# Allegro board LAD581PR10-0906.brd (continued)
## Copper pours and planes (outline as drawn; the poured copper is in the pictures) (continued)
PWR_VGA_CORE_LGATE1 on IN1 (solid shape): 238.9,60.54 237.95,59.59 237.31,59.59 237.12,59.78 237.12,60.22 238.14,61.24 238.9,61.24
PWR_VGA_CORE_LGATE1 on IN1 (solid shape): 250.52,62.06 251.41,62.06 251.73,61.75 251.73,61.37 251.6,61.24 249.25,61.24 249,61.49 249,61.68 249.7,62.38 250.2,62.38
PWR_VGA_CORE_LGATE2 on TOP (solid shape): 251.73,62.7 252.68,62.7 252.73,62.65 252.73,62.49 252.68,62.44 250.65,62.44 250.52,62.57 250.52,62.83 250.65,62.95 251.47,62.95
PWR_VGA_CORE_LGATE2 on TOP (solid shape): 240.58,68.02 240.58,67.44 240.81,67.21 240.81,66.51 240.68,66.38 239.66,66.38 239.35,66.7 239.35,67.94 239.56,68.16 240.44,68.16
PWR_VGA_CORE_LGATE2 on IN1 (solid shape): 240.87,67.14 240.87,64.86 240.7,64.7 239.76,64.7 239.65,64.81 239.65,66.11 239.66,66.13 239.66,67.02 239.85,67.21 240.81,67.21
PWR_VGA_CORE_LGATE2 on IN1 (solid shape): 251.86,63.46 251.86,62.64 251.6,62.38 250.71,62.38 250.46,62.64 249.82,62.64 249.51,62.95 249.51,63.4 249.82,63.71 251.6,63.71
PWR_VGA_CORE_PHASE1 on TOP (solid shape): 252.73,61.42 252.73,61.29 251.4,59.96 249.49,59.96 249.39,60.06 249.39,60.7 249.48,60.79 250.97,60.79 251.66,61.49 252.66,61.49
PWR_VGA_CORE_PHASE1 on TOP (solid shape): 241.38,64.48 241.38,60.56 242.58,59.35 242.58,57.09 242.3,56.8 237.2,56.8 236.95,57.06 236.95,59.05 237.18,59.29 238.15,59.29 238.51,59.65 238.51,64.54 238.63,64.67 241.19,64.67
PWR_VGA_CORE_PHASE1 on BOTTOM (solid shape): 242.58,63.24 242.58,58.06 242.39,57.87 238.64,57.87 238.46,58.06 238.46,63.16 238.83,63.53 242.3,63.53
PWR_VGA_CORE_PHASE1 on IN1 (solid shape): 242.52,60.22 242.52,59.21 242.39,59.08 241.63,59.08 241.5,59.21 241.5,60.16 241.7,60.35 242.39,60.35
PWR_VGA_CORE_PHASE1 on IN1 (solid shape): 251.92,60.67 251.92,60.48 251.16,59.71 249.76,59.71 249.44,60.03 249.44,60.79 249.63,60.98 251.6,60.98
PWR_VGA_CORE_PHASE2 on TOP (solid shape): 251.92,64.22 251.92,63.84 252.73,63.04 252.73,62.93 252.66,62.87 251.75,62.87 250.9,63.71 249.7,63.71 249.63,63.78 249.63,64.41 249.7,64.48 251.66,64.48
PWR_VGA_CORE_PHASE2 on TOP (solid shape): 244.49,73.87 244.49,72.29 244.04,71.84 243.73,71.84 243.6,71.72 243.6,67.65 243.73,67.52 244.04,67.52 244.17,67.4 244.17,65.68 243.92,65.43 241.19,65.43 241.06,65.56 241.06,67.3 240.73,67.63 240.73,71.92 242.08,73.27 242.08,74.32 242.14,74.38 243.98,74.38
PWR_VGA_CORE_PHASE2 on BOTTOM (solid shape): 244.87,72.8 244.87,66.11 244.51,65.75 244.49,65.75 244.17,65.43 241.19,65.43 240.93,65.68 240.93,67.02 240.81,67.14 239.34,67.14 239.31,67.12 238.6,67.12 238.55,67.16 238.55,70.71 238.59,70.74 239.13,70.74 241.31,72.92 241.63,72.92 242.08,73.37 244.3,73.37
PWR_VGA_CORE_PHASE2 on IN1 (solid shape): 251.92,65.18 251.92,63.97 251.86,63.91 250.78,63.91 250.52,64.16 250.52,65.24 250.71,65.43 251.66,65.43
PWR_VGA_CORE_PHASE2 on IN1 (solid shape): 245.49,66.42 245.49,65.69 245.14,65.35 241.33,65.35 241.06,65.62 241.06,66.76 241.19,66.89 241.2,66.88 241.58,66.88 241.59,66.89 245.02,66.89
PWR_VGA_CORE_UGATE1 on TOP (solid shape): 244.3,60.73 244.3,59.84 244.17,59.71 243.35,59.71 243.16,59.9 243.16,60.98 243.22,61.05 243.98,61.05
PWR_VGA_CORE_UGATE1 on TOP (solid shape): 253.55,61.02 253.55,59.9 253.51,59.86 253.51,58.95 253.44,58.89 253.11,58.89 253.04,58.97 253.04,59.89 253.32,60.17 253.32,61.02 253.38,61.08 253.49,61.08
PWR_VGA_CORE_UGATE1 on IN1 (solid shape): 245.25,60.41 245.25,60.03 244.93,59.71 243.35,59.71 243.09,59.97 243.09,60.54 243.28,60.73 244.93,60.73
PWR_VGA_CORE_UGATE1 on IN1 (solid shape): 253.76,59.9 253.76,59.02 253.38,58.63 252.11,58.63 251.86,58.89 251.86,59.84 252.11,60.1 253.57,60.1
PWR_VGA_CORE_UGATE2 on TOP (solid shape): 247.66,68.54 247.66,67.84 247.16,67.33 245.51,67.33 245.38,67.46 245.38,68.1 245.51,68.22 246.65,68.22 247.16,68.73 247.47,68.73
PWR_VGA_CORE_UGATE2 on TOP (solid shape): 253.62,65.44 253.62,65.28 253.63,65.28 253.63,64.54 253.54,64.44 253.54,63.33 253.48,63.27 253.38,63.27 253.32,63.33 253.32,64.35 253.13,64.54 253.13,65.43 253.25,65.56 253.51,65.56
PWR_VGA_CORE_UGATE2 on IN1 (solid shape): 253.82,65.68 253.82,64.48 253.63,64.29 252.81,64.29 252.17,64.92 252.17,66.19 252.49,66.51 253,66.51
PWR_VGA_CORE_UGATE2 on IN1 (solid shape): 248.93,68.6 248.93,67.97 248.74,67.78 246.84,67.78 246.65,67.97 246.65,68.6 246.87,68.83 248.71,68.83
RING2 on BOTTOM (solid shape): 18.43,17.49 18.43,16.41 18.35,16.33 16.68,16.33 16.65,16.36 16.65,17.59 16.88,17.82 18.09,17.82
RING2 on BOTTOM (solid shape): 21.92,38.52 23.44,38.52 23.51,38.46 23.51,38.33 23.44,38.27 21.98,38.27 21.86,38.14 20.97,38.14 20.84,38.27 20.84,38.52 20.97,38.65 21.79,38.65
RING2 on IN5 (solid shape): 21.98,38.46 21.98,38.21 20.9,37.13 19.89,37.13 19.89,37.51 21.03,38.65 21.79,38.65
RING2 on IN5 (solid shape): 18.05,18.78 18.05,17.38 17.92,17.25 17.09,17.25 16.9,17.44 16.9,18.43 17.38,18.9 17.92,18.9
RING2_R on BOTTOM (solid shape): 16.99,19.32 16.99,18.24 16.49,17.73 16.49,15.86 16.94,15.41 16.96,15.39 16.96,14.91 16.97,14.91 16.97,13.96 16.82,13.81 16.22,13.81 16.08,13.96 16.08,14.38 16.1,14.4 16.1,15.09 15.79,15.39 15.79,16.44 15.61,16.62 15.01,16.62 14.91,16.72 14.91,17.31 15.34,17.74 15.34,18.21 15.33,18.22 15.33,18.54 15.89,19.1 15.89,19.37 16.04,19.52 16.79,19.52
RING2_R on IN3 (solid shape): 16.94,19.38 16.94,18.6 16.65,18.31 16.19,18.31 15.9,18.6 15.9,19.37 16.05,19.52 16.8,19.52
RING2_R on IN5 (solid shape): 16.94,19.39 16.94,18.87 16.47,18.4 16.04,18.4 15.86,18.58 15.86,19.4 16,19.54 16.79,19.54
RJ45_CT on BOTTOM (solid shape): 225.87,158.96 225.87,156.35 225.68,156.16 224.6,156.16 224.35,156.42 224.35,158.07 222.75,159.66 210.81,159.66 210.77,159.7 210.77,160.36 211.15,160.74 224.09,160.74
RT8812_PVCC on TOP (solid shape): 249.44,64.16 249.44,63.78 250.14,63.08 250.33,63.08 250.39,63.02 250.39,62.51 250.59,62.32 252.68,62.32 252.73,62.27 252.73,62.11 252.68,62.06 249.76,62.06 249.51,62.32 249.51,62.83 249.12,63.21 248.62,63.21 248.43,63.4 248.43,64.16 248.49,64.22 249.38,64.22
SLEEVE on BOTTOM (solid shape): 18.49,22.06 18.49,21.11 18.23,20.85 16.84,20.85 16.65,21.04 16.65,22.18 16.71,22.24 18.31,22.24
SLEEVE on BOTTOM (solid shape): 22.17,38.91 23.44,38.91 23.51,38.84 23.51,38.72 23.44,38.65 21.98,38.65 21.86,38.78 20.78,38.78 20.31,38.31 19.51,38.31 19.38,38.44 19.38,38.78 19.7,39.1 21.98,39.1
SLEEVE on IN5 (solid shape): 17.79,21.82 17.79,20.94 17.67,20.81 16.84,20.81 16.65,21 16.65,21.57 16.14,22.08 16.14,22.71 16.33,22.9 16.71,22.9
SLEEVE on IN5 (solid shape): 20.51,38.64 20.51,38.45 19.19,37.13 18.74,37.13 18.49,37.38 18.49,37.76 19,38.27 19,38.33 19.49,38.82 20.33,38.82
SLEEVE_R on BOTTOM (solid shape): 16.47,23.12 16.47,20.87 16.89,20.45 16.89,20.03 16.6,19.73 16.02,19.73 15.71,19.43 15.71,19.2 15.57,19.06 14.84,19.06 14.64,19.25 14.64,19.58 15.36,20.29 15.36,20.98 14.98,21.36 14.98,21.91 15.01,21.93 15.57,21.93 15.76,22.12 15.76,23.11 15.87,23.22 16.38,23.22
SLEEVE_R on IN1 (solid shape): 15.71,19.39 15.71,18.74 15.34,18.38 15.03,18.38 14.66,18.74 14.66,19.39 14.8,19.53 15.57,19.53
SLEEVE_R on IN4 (solid shape): 15.72,19.38 15.72,18.25 15.52,18.05 15.43,18.05 14.66,18.82 14.66,19.39 14.81,19.54 15.56,19.54
SNB_VCCIO on BOTTOM (solid shape): 94.99,99.37 94.99,98.3 94.63,97.94 94.63,97.07 94.56,97.01 94.06,97.01 93.11,97.96 93.11,99.27 93.26,99.43 94.94,99.43
SPK_L+_CONN on TOP (solid shape): 39.36,11.36 39.36,10.7 39.3,10.64 38.97,10.64 38.71,10.38 38.07,10.38 37.93,10.24 36.5,10.24 36.4,10.34 36.4,11.14 36.97,11.7 39.02,11.7
SPK_L+_CONN on TOP (solid shape): 29.96,13.75 29.96,13.06 30.22,12.81 31,12.81 31.25,12.55 31.25,11.85 31.19,11.79 28.65,11.79 28.4,12.05 28.4,12.61 28.45,12.66 29.24,12.66 29.36,12.79 29.36,13.74 29.41,13.79 29.92,13.79
SPK_L+_CONN on TOP (solid shape): 22.6,28.15 22.6,27.94 22.45,27.79 22.43,27.77 22.08,27.77 22.05,27.74 22.04,27.74 22.03,27.74 22.01,27.74 22.01,27.72 21.86,27.57 21.86,27.13 21.81,27.08 21.28,27.08 21.24,27.12 21.24,27.61 21.33,27.71 21.34,27.71 21.41,27.77 21.47,27.84 21.48,27.85 21.53,27.9 21.53,27.94 21.56,27.97 21.56,28.15 21.67,28.26 22.5,28.26
SPK_L+_CONN on BOTTOM (solid shape): 40.23,13.07 40.23,10.78 39.9,10.45 38.49,10.45 38.34,10.59 38.34,10.82 38.57,11.04 38.71,11.04 39.34,11.67 39.34,13.05 39.52,13.23 40.08,13.23
SPK_L+_CONN on IN2 (solid shape): 22.62,28.24 22.62,26.47 22.37,26.22 21.54,27.05 21.54,28.17 21.67,28.3 22.55,28.3
SPK_L+_CONN on IN2 (solid shape): 28.7,13.01 30,13.01 30.21,12.81 30.21,12.11 30.08,11.98 28.33,11.98 28.02,12.3 28.02,12.43 28.37,12.78 28.37,13.06 28.43,13.12 28.59,13.12
SPK_L-_CONN on TOP (solid shape): 33.6,14.2 33.6,13.7 34.62,12.68 34.62,12.55 34.11,12.05 33.73,12.05 32.52,13.25 32.52,14.27 32.59,14.33 33.48,14.33
SPK_L-_CONN on TOP (solid shape): 38.35,9.22 40.72,9.22 40.72,8.17 36.28,8.17 35.93,8.52 35.93,9.35 36.12,9.54 38.03,9.54
SPK_L-_CONN on TOP (solid shape): 24.38,28.12 24.38,27.81 24.44,27.75 24.44,27.08 24.41,27.05 23.86,27.05 23.75,27.16 23.75,27.65 23.62,27.78 23.46,27.78 23.34,27.89 23.34,28.14 23.46,28.26 24.24,28.26
SPK_L-_CONN on BOTTOM (solid shape): 33.98,15.73 33.98,13.32 33.86,13.19 32.71,13.19 32.59,13.32 32.59,15.86 32.65,15.92 33.79,15.92
SPK_L-_CONN on BOTTOM (solid shape): 41.52,13.02 41.52,9.35 40.63,8.46 36.04,8.46 35.95,8.55 35.95,9.39 36.12,9.57 40.1,9.57 40.5,9.97 40.5,13 40.74,13.23 41.31,13.23
SPK_L-_CONN on IN2 (solid shape): 33.37,15.2 33.37,13.25 33.31,13.19 32.59,13.19 32.46,13.32 32.46,14.71 32.08,15.09 32.08,15.16 32.59,15.66 32.91,15.66
SPK_L-_CONN on IN2 (solid shape): 24.43,28.14 24.43,27.67 24.73,27.37 24.73,26.5 24.46,26.24 23.84,26.24 23.71,26.36 23.71,27.16 23.35,27.52 23.35,28.2 23.41,28.26 24.3,28.26
SPK_L-_CONN on IN2 (solid shape): 25.1,24.79 25.1,23.63 25.07,23.62 24.87,23.29 25.07,22.97 25.1,22.96 25.1,22.25 25.07,22.24 24.87,21.91 25.07,21.59 25.1,21.58 25.1,20.87 25.07,20.85 24.87,20.53 25.07,20.21 25.1,20.2 25.1,19.49 25.07,19.47 24.9,19.01 25.36,18.83 25.39,18.84 25.6,18.63 25.73,18.63 25.8,18.57 25.8,17.87 25.54,17.61 25.1,17.61 24.08,18.63 24.08,18.89 24.2,19.15 24.08,19.42 24.08,20.27 24.2,20.53 24.08,20.8 24.08,21.65 24.2,21.91 24.08,22.18 24.08,23.03 24.2,23.29 24.08,23.56 24.08,24.15 23.7,24.54 23.7,24.98 23.89,25.17 24.72,25.17
SPK_R+_CONN on TOP (solid shape): 39.49,7.51 39.49,6.87 39.36,6.75 38.35,6.75 38.03,6.43 36.12,6.43 35.93,6.62 35.93,7.44 36.12,7.63 39.36,7.63
SPK_R+_CONN on TOP (solid shape): 20.46,23.48 20.46,22.94 20.39,22.86 20.39,22.73 20.39,22.73 20.39,21.97 20.39,21.97 20.39,21.82 20.39,21.81 20.33,21.76 20.33,21.75 20.24,21.65 19.9,21.65 19.78,21.77 19.78,23.47 19.82,23.51 20.44,23.51
SPK_R+_CONN on BOTTOM (solid shape): 21.54,13.32 20.71,12.49 20.08,12.49 19.89,12.68 19.89,13.57 20.01,13.7 20.4,13.7 20.78,14.08 20.78,14.33 20.84,14.39 21.54,14.39
SPK_R+_CONN on BOTTOM (solid shape): 42.85,13.03 42.85,7.66 41.72,6.53 38.45,6.53 38.37,6.62 38.37,7.3 38.49,7.42 41.05,7.42 41.84,8.21 41.84,13.02 42.04,13.22 42.66,13.22
SPK_R+_CONN on IN1 (solid shape): 20.83,22.62 20.83,20.9 20.56,20.63 20.01,20.63 19.83,20.81 19.83,22.69 19.95,22.82 20.64,22.82
SPK_R+_CONN on IN1 (solid shape): 20.84,13.79 20.84,13.49 21.11,13.23 21.11,12.9 20.7,12.49 20.07,12.49 19.82,12.73 19.82,13.71 20.03,13.91 20.71,13.91
SPK_R+_CONN on IN5 (solid shape): 21.92,12.55 21.92,11.98 21.6,11.66 21.41,11.66 20.65,12.43 20.27,12.43 20.01,12.68 20.01,12.87 20.4,13.25 21.22,13.25
SPK_R+_CONN on IN5 (solid shape): 36.63,7.44 36.63,6.09 36.33,5.79 36.05,5.79 35.99,5.73 35.38,5.73 35.09,6.01 35.09,6.68 35.35,6.94 35.77,6.94 35.9,7.07 35.9,7.41 36.07,7.58 36.49,7.58
SPK_R-_CONN on TOP (solid shape): 22.94,14.08 22.94,12.93 22.81,12.81 21.58,12.81 21.4,12.99 21.4,14.2 21.41,14.2 22.81,14.2
SPK_R-_CONN on TOP (solid shape): 20.49,24.76 20.49,24.28 20.81,23.96 20.81,23.75 20.71,23.66 19.83,23.66 19.74,23.75 19.74,24.71 19.83,24.8 20.44,24.8
SPK_R-_CONN on TOP (solid shape): 38.35,5.22 39.36,5.22 39.49,5.09 39.49,4.46 39.36,4.33 36.12,4.33 35.93,4.52 35.93,5.35 36.12,5.54 38.03,5.54
SPK_R-_CONN on BOTTOM (solid shape): 44.06,13.05 44.06,6.56 42.12,4.62 39.95,4.62 39.76,4.42 38.48,4.42 38.37,4.53 38.37,5.2 38.84,5.68 41.62,5.68 43.11,7.16 43.11,13.03 43.3,13.22 43.89,13.22
SPK_R-_CONN on IN2 (solid shape): 22.99,14.05 22.99,12.84 22.92,12.76 21.96,12.76 21.86,12.86 21.86,13.26 21.95,13.35 21.95,14.12 22.21,14.38 22.66,14.38
SPK_R-_CONN on IN2 (solid shape): 21.58,23.48 21.58,22.55 21.19,22.16 20.75,22.16 20.56,22.35 20.56,22.81 19.75,23.63 19.75,23.97 20.17,24.38 20.68,24.38
SPK_R-_CONN on IN5 (solid shape): 37.86,5.25 37.86,4.68 37.57,4.39 36.14,4.39 36.03,4.5 36.04,4.51 36.04,5.42 36.16,5.54 36.6,5.54 36.77,5.7 37.41,5.7
SPK_R-_CONN on IN5 (solid shape): 24.02,14.01 24.02,13.25 23.97,13.2 23.3,13.2 22.87,12.78 22.14,12.78 21.86,13.06 21.86,13.47 22.59,14.2 23.82,14.2
SW_1.2V on TOP (solid shape): 63.31,49.96 63.31,49.81 63.95,49.18 63.95,47.17 63.85,47.07 63.29,47.07 63.2,47.16 63.2,49.06 62.41,49.85 62.41,49.96 62.48,50.03 63.25,50.03
SW_1.2V on TOP (solid shape): 72.81,54.39 72.81,51.88 73.36,51.33 75,51.33 75,50.31 74.87,50.18 73.6,50.18 72.78,49.35 69.35,49.35 69.03,49.67 69.03,50.69 68.84,50.88 67.31,50.88 67.18,51.01 67.18,51.79 67.28,51.89 68.89,51.89 71.68,54.68 72.53,54.68
SW_1.2V on BOTTOM (solid shape): 72.85,54.42 72.85,51.29 73.2,50.93 73.2,49.99 72.53,49.32 68.38,49.32 67.6,50.1 67.6,50.92 66.66,51.85 66.66,54.44 67.09,54.87 72.4,54.87
SW_1.2V on IN1 (solid shape): 70.17,49.86 70.17,49.04 69.47,48.34 68.58,48.34 68.39,48.53 68.39,49.16 69.22,49.99 70.04,49.99
SW_1.2V on IN1 (solid shape): 63.93,49.3 65.1,49.3 65.27,49.13 65.27,48.55 65.04,48.33 63.94,48.33 63.01,49.25 63.01,49.57 63.12,49.68 63.54,49.68
SW_+1VALWP on TOP (solid shape): 211.81,20.21 211.81,20.01 211.72,19.92 210.58,19.92 210.13,19.47 208.67,19.47 208.55,19.6 208.55,20.24 208.61,20.3 211.72,20.3
SW_+1VALWP on BOTTOM (solid shape): 205.63,24.87 205.63,20.43 205.43,20.24 203.53,20.24 203.21,19.92 203.21,18.84 203.4,18.65 204.23,18.65 204.42,18.46 204.42,17 201.88,14.46 197.31,14.46 197.12,14.65 197.12,17.76 197.43,18.07 199.95,18.07 201.98,20.1 201.98,22.58 202.3,22.9 203.78,22.9 204.16,23.28 204.16,25.06 204.29,25.19 205.31,25.19
SW_+1VALWP on IN5 (solid shape): 204.16,21.95 204.16,21.25 203.91,21 202.89,21 202.77,21.13 202.77,21.95 202.89,22.08 204.04,22.08
SW_+1VALWP on IN5 (solid shape): 210.58,20.17 210.58,19.92 209.05,18.4 208.29,18.4 207.97,18.71 207.97,18.97 208.42,19.41 209.05,19.41 209.94,20.3 210.45,20.3
TBT_SVR_IND on TOP (solid shape): 144.01,159.77 144.6,159.77 144.66,159.71 144.66,159.58 144.6,159.52 144.47,159.52 144.28,159.33 144.28,159.2 144.23,159.15 143.8,159.15 143.78,159.16 143.72,159.19 143.66,159.2 143.57,159.2 142.82,159.2 142.69,159.08 142.69,159.08 142.52,159.08 142.38,159.22 142.38,160.26 142.57,160.45 143.33,160.45
TBT_SVR_IND on BOTTOM (solid shape): 142.78,161.69 142.9,161.56 143.07,161.5 143.3,161.27 143.34,161.2 143.39,161.13 143.39,159.31 143.19,159.1 142.42,159.1 142.18,158.86 142.18,157.96 142.09,157.87 140.74,157.87 140.67,157.95 140.67,161.69
TBTA_CC1 on BOTTOM (solid shape): 128.17,156.87 128.17,156.8 128.16,156.79 128.16,156.52 128.17,156.51 128.17,156.34 128.65,156.34 128.72,156.27 128.72,155.44 128.68,155.4 128.39,155.11 128.39,155.09 127.96,154.66 127.94,154.66 127.87,154.74 127.87,155.08 127.89,155.21 127.87,155.33 127.87,155.83 127.65,156.04 127.65,156.73 127.81,156.89 128.14,156.89
UG_3V on TOP (solid shape): 47.51,37.17 47.51,36.66 47.36,36.51 47.05,36.51 46.73,36.2 46.73,35.95 46.59,35.81 46.36,35.81 46.24,35.92 46.24,36.68 46.86,37.31 47.37,37.31
UG_3V on BOTTOM (solid shape): 36.46,30.14 36.46,29.7 35.41,28.65 35.26,28.65 35.2,28.71 35.2,29.52 36.02,30.33 36.27,30.33
UG_3V on IN5 (solid shape): 46.75,36.68 46.75,35.86 46.62,35.73 45.41,35.73 45.1,36.05 45.1,36.49 45.41,36.81 46.62,36.81
UG_3V on IN5 (solid shape): 37.92,31.22 37.92,30.97 36.97,30.02 36.84,30.02 36.14,29.32 35.7,29.32 35.51,29.51 35.51,29.95 37.22,31.67 37.48,31.67
UG_5V on TOP (solid shape): 48.15,24.05 48.15,23.2 47.58,22.63 46.52,22.63 46.37,22.78 46.37,24.11 46.49,24.24 47.95,24.24
UG_5V on BOTTOM (solid shape): 35.95,25.85 36.4,25.85 36.6,25.65 36.6,25.32 36.49,25.21 36.1,25.21 36.09,25.2 35.43,25.2 35.2,25.43 35.2,26.38 35.28,26.46 35.34,26.46
UG_5V on IN5 (solid shape): 37.54,24.87 37.54,24.49 37.1,24.05 36.65,24.05 35.51,25.19 35.51,25.57 35.64,25.7 36.72,25.7
UG_5V on IN5 (solid shape): 48.15,24.17 48.15,23.28 47.95,23.09 47.57,23.09 46.62,24.05 46.18,24.05 46.11,24.11 46.11,25.06 47.26,25.06
UG_+1VALWP on TOP (solid shape): 211.81,19.71 211.81,19.5 211.72,19.41 210.96,19.41 210.26,18.71 210.01,18.71 209.88,18.84 209.88,19.03 210.51,19.67 210.64,19.67 210.77,19.79 211.72,19.79
UG_+1VALWP on BOTTOM (solid shape): 204.48,19.79 204.48,19.06 204.29,18.87 203.5,18.87 203.34,19.03 203.34,19.79 203.48,19.94 204.34,19.94
UG_+1VALWP on IN5 (solid shape): 204.48,19.73 204.48,18.4 204.29,18.2 203.78,18.2 203.28,18.71 203.28,19.73 203.47,19.92 204.29,19.92
UG_+1VALWP on IN5 (solid shape): 211.09,19.35 211.09,18.71 209.37,17 208.42,17 208.42,17.89 208.55,18.01 208.93,18.01 210.58,19.67 210.77,19.67
VL on BOTTOM (solid shape): 37.31,27.79 38.18,27.79 38.24,27.73 38.24,27.15 38.18,27.09 37.29,27.09 37.28,27.1 37.28,27.4 37.15,27.53 36.79,27.53 36.7,27.45 35.66,27.45 35.62,27.49 35.62,27.6 35.68,27.66 36.63,27.66 36.77,27.79 37.31,27.79
N150987 on BOTTOM (solid shape): 25.54,45.93 25.54,45.12 25.27,44.86 25.27,44.06 25.57,43.76 25.57,42.49 25.31,42.24 25.31,41.34 25.26,41.29 25.16,41.29 25.11,41.34 25.11,42.91 24.55,43.47 24.55,45.91 24.61,45.97 25.51,45.97
N151025 on TOP (solid shape): 28.39,44.83 29.25,44.83 29.3,44.78 29.3,44.16 29.25,44.1 28.4,44.1 27.89,43.6 27.89,42.85 27.47,42.43 27.05,42.43 26.87,42.61 26.87,42.87 27.13,43.13 27.13,44.77 27.29,44.93 28.28,44.93
N155531 on TOP (solid shape): 30.97,18.71 31.57,18.71 31.7,18.59 31.7,18.33 31.57,18.2 30.75,18.2 30.05,18.9 29.08,18.9 29.01,18.97 29.01,19.07 29.07,19.14 30.54,19.14
N155531 on BOTTOM (solid shape): 31.7,18.59 31.7,18.33 30.96,17.59 29.78,17.59 29.69,17.68 29.69,18.59 29.82,18.71 31.57,18.71
N155533 on TOP (solid shape): 26.2,18.06 26.2,16.02 26.34,15.89 26.67,15.89 26.76,15.8 26.76,15.17 26.76,15.17 26.76,15.04 26.7,14.97 26.05,14.97 26,15.02 26,18.06 26.05,18.11 26.15,18.11
N155535 on TOP (solid shape): 25.81,18.06 25.81,17.2 25.86,17.15 25.86,15.95 25.66,15.75 25.66,15.06 25.59,15 24.9,15 24.9,15.77 25,15.87 25.4,15.87 25.63,16.1 25.63,16.99 25.6,17.02 25.6,18.06 25.66,18.11 25.76,18.11
N155537 on TOP (solid shape): 22.81,19.07 22.81,18.97 22.75,18.9 21.92,18.9 21.49,18.47 21.49,17.66 21.33,17.5 20.9,17.5 20.78,17.62 20.78,18.52 20.93,18.67 21.33,18.67 21.8,19.13 22.75,19.13
N155537 on BOTTOM (solid shape): 21.41,18.31 21.41,17.56 21.06,17.21 21.06,16.88 21.41,16.52 21.41,15.73 21.35,15.66 20.65,15.66 20.37,15.94 20.37,18.16 20.65,18.44 21.28,18.44
N155763 on BOTTOM (solid shape): 29.86,13.44 29.86,12.93 29.73,12.81 28.46,12.81 28.27,13 28.27,13.51 28.33,13.57 29.73,13.57
N155773 on TOP (solid shape): 28.09,14.62 28.09,14.18 27.23,13.32 26.61,13.32 26.53,13.4 26.53,14.05 27.21,14.72 27.99,14.72
N155779 on TOP (solid shape): 25.46,14.45 25.46,13.03 25.34,12.9 24.78,12.9 24.69,12.99 24.69,13.8 24.47,14.02 24.05,14.02 23.98,14.1 23.98,14.63 24.06,14.71 25.21,14.71
N155789 on BOTTOM (solid shape): 21.48,15.41 21.48,14.71 21.41,14.65 19.95,14.65 19.89,14.71 19.89,15.41 19.95,15.47 21.41,15.47
N3691692 on TOP (solid shape): 209.63,18.78 209.63,16.93 209.56,16.87 208.93,16.87 208.86,16.93 208.86,17.89 208.55,18.2 208.55,18.84 208.61,18.9 209.5,18.9
N3691782 on BOTTOM (solid shape): 208.93,25.06 208.93,24.3 208.86,24.24 208.23,24.24 208.04,24.05 208.04,23.6 207.91,23.48 206.96,23.48 206.9,23.54 206.9,25.13 207.02,25.25 208.74,25.25
N4123582 on TOP (solid shape): 43.32,19.98 43.32,19.28 43.19,19.16 40.27,19.16 40.14,19.28 40.14,20.05 40.33,20.24 43.07,20.24
N17230071 on BOTTOM (solid shape): 216.18,35.23 216.18,33.94 216.28,33.84 216.75,33.84 216.86,33.73 216.86,32.97 216.79,32.9 215.53,32.9 215.36,33.07 215.36,35.28 215.46,35.38 216.03,35.38
N17847188 on BOTTOM (solid shape): 165.24,151.94 165.24,151.09 164.66,150.51 164.66,148.73 163.97,148.04 162.7,148.04 162.57,148.17 162.57,148.61 163.4,149.44 163.4,151.68 163.72,152 165.18,152
N17847698 on BOTTOM (solid shape): 168.73,155.54 168.73,154.96 168.62,154.85 168.43,154.85 168.29,154.71 168.29,154.27 168.01,153.99 166.99,153.99 166.89,153.88 166.89,153.69 166.57,153.38 165.81,153.38 165.75,153.44 165.75,154.04 165.88,154.17 165.88,154.2 166.13,154.46 167.18,154.46 167.34,154.42 167.5,154.46 167.59,154.46 167.65,154.52 167.65,154.61 167.69,154.77 167.65,154.94 167.65,155.15 168.1,155.6 168.67,155.6
N17848703 on BOTTOM (solid shape): 167.02,149.01 167.02,148.38 166.95,148.32 164.92,148.32 164.86,148.38 164.86,149.01 164.92,149.08 166.95,149.08
N17848716 on BOTTOM (solid shape): 165.81,151.87 165.81,149.84 165.75,149.78 164.86,149.78 164.79,149.84 164.79,150.41 164.86,150.48 165.24,150.48 165.43,150.67 165.43,151.94 165.49,152 165.68,152
N18456772 on TOP (solid shape): 60.15,33 60.15,32.62 61.16,31.6 61.16,30.71 61.1,30.65 60.15,30.65 60.08,30.71 60.08,31.63 59.5,32.22 59.5,33.27 59.56,33.34 59.81,33.34
N19496810 on BOTTOM (solid shape): 242.71,151.6 242.71,147.47 242.01,146.77 240.68,146.77 240.62,146.84 240.62,147.22 241.12,147.73 241.12,151.92 241.19,151.98 242.33,151.98
N19497031 on BOTTOM (solid shape): 239.09,149.88 239.09,148.11 239.03,148.04 238.52,148.04 238.46,148.11 238.46,148.55 238.01,149 238.01,149.76 238.2,149.95 239.03,149.95
N19534529 on BOTTOM (solid shape): 203.91,35.27 203.91,33.36 203.85,33.3 203.02,33.3 202.96,33.36 202.96,35.2 203.09,35.33 203.85,35.33
N19534538 on BOTTOM (solid shape): 197.5,35.14 197.5,34.31 197.12,33.93 197.12,33.3 197.05,33.23 196.23,33.23 196.17,33.3 196.17,34.57 196.8,35.2 197.44,35.2
N20881570 on BOTTOM (solid shape): 94.12,104.54 94.12,103.59 94.06,103.53 93.42,103.53 92.36,104.59 92.36,105.6 92.44,105.68 92.98,105.68
N20904379 on BOTTOM (solid shape): 126.7,149.13 126.7,148.93 126.89,148.74 127.08,148.74 127.2,148.61 127.2,147.52 128.35,146.38 128.35,145.91 128.29,145.85 127.81,145.85 127.65,146.01 127.65,146.14 126.19,147.6 126.19,148.17 125.93,148.42 125.93,148.61 126.06,148.74 126.21,148.74 126.38,148.91 126.38,149.12 126.48,149.22 126.61,149.22
N21146007 on TOP (solid shape): 204.99,36.41 204.99,35.14 204.93,35.08 203.53,35.08 203.09,35.52 203.09,36.41 203.15,36.47 204.93,36.47
N21146153 on TOP (solid shape): 199.98,36.41 199.98,35.65 199.91,35.58 199.47,35.58 198.96,35.08 198.07,35.08 198.01,35.14 198.01,36.41 198.07,36.47 199.91,36.47
N21146805 on TOP (solid shape): 218.4,35.6 218.4,35.02 217.63,34.25 216.36,34.25 216.3,34.31 216.3,35.58 216.36,35.65 218.35,35.65
N29425467 on BOTTOM (solid shape): 145.96,132.37 145.96,131.23 146.08,131.1 149.83,131.1 149.96,130.97 149.96,127.83 149.81,127.68 149.81,126.96 149.68,126.83 145.28,126.83 144.99,127.11 144.99,132.43 145.12,132.56 145.77,132.56
N29425497 on BOTTOM (solid shape): 137.99,132.34 137.99,131.2 138.12,131.07 141.87,131.07 141.99,130.95 141.99,126.98 141.82,126.8 137.31,126.8 137.03,127.09 137.03,132.41 137.16,132.54 137.8,132.54
N29425633 on BOTTOM (solid shape): 129.47,132.44 129.47,131.25 129.64,131.09 133.35,131.09 133.43,131.01 133.43,129.83 134.31,128.95 134.31,126.73 134.25,126.66 129.71,126.66 128.51,127.87 128.51,132.38 128.65,132.52 129.39,132.52
N29435109 on TOP (solid shape): 157.88,123.66 157.88,122.26 157.68,122.07 155.65,122.07 155.4,122.33 155.4,123.72 155.53,123.85 157.68,123.85
N29435109 on BOTTOM (solid shape): 157.75,123.49 157.75,121.31 157.39,120.95 153.24,120.95 152.98,121.2 152.98,124 154.06,125.08 156.16,125.08
N29435333 on BOTTOM (solid shape): 121.34,132.45 121.34,131.28 121.47,131.15 125.22,131.15 125.34,131.02 125.34,129.65 125.85,129.14 126.69,129.14 126.82,129.01 126.82,126.98 126.63,126.79 121.08,126.79 120.87,127 120.87,128.65 120.38,129.14 120.38,132.45 120.48,132.55 121.25,132.55
N29435335 on TOP (solid shape): 154,123.72 154,122.26 153.87,122.13 151.59,122.13 151.53,122.2 151.53,122.83 151.59,122.9 152.6,122.9 152.73,123.02 152.73,123.72 152.86,123.85 153.87,123.85
N29436554 on BOTTOM (solid shape): 113.01,132.37 113.01,131.19 113.14,131.06 116.89,131.06 117.01,130.94 117.01,129.52 117.52,129.01 119.01,129.01 119.07,128.95 119.07,126.85 119.01,126.79 112.33,126.79 112.05,127.07 112.05,132.34 112.17,132.47 112.92,132.47
N31245253 on TOP (solid shape): 262.71,62.38 262.71,61.43 262.65,61.37 262.65,60.71 262.65,60.7 262.61,60.54 262.65,60.38 262.65,60.37 262.65,60.03 262.53,59.91 262.43,59.92 262.39,59.93 262.21,59.93 262.15,59.92 262.09,59.9 261.7,59.9 261.51,60.1 261.51,62.32 261.76,62.57 262.52,62.57
N31413382 on BOTTOM (solid shape): 90.18,103.68 90.18,102.79 90.12,102.72 88.4,102.72 88.28,102.85 88.28,103.68 88.34,103.74 90.12,103.74
N31426894 on BOTTOM (solid shape): 132.59,137.28 132.59,136.64 131.94,135.99 131.94,135.27 131.84,135.17 131.69,135.17 131.6,135.27 131.6,137.27 131.67,137.34 132.52,137.34
N31426895 on BOTTOM (solid shape): 133.82,138.73 133.85,138.7 133.85,138.14 133.8,138.09 131.65,138.09 131.6,138.14 131.6,138.68 131.65,138.73 133.78,138.73
N31426896 on BOTTOM (solid shape): 133.87,137.25 133.87,136.57 133.67,136.37 133.2,136.37 132.92,136.08 132.92,135.25 132.85,135.19 132.66,135.19 132.6,135.25 132.6,136.28 132.92,136.6 132.92,137.26 132.97,137.32 133.81,137.32
N31432086 on BOTTOM (solid shape): 142.34,138.66 142.38,138.63 142.38,138.07 142.33,138.02 140.18,138.02 140.13,138.07 140.13,138.61 140.18,138.66 142.31,138.66
N31432111 on BOTTOM (solid shape): 141.11,137.23 141.11,136.59 140.46,135.94 140.46,135.3 140.33,135.18 140.2,135.18 140.14,135.24 140.14,137.24 140.2,137.29 141.05,137.29
N31432114 on BOTTOM (solid shape): 142.39,137.2 142.39,136.52 142.19,136.31 141.72,136.31 141.44,136.03 141.44,135.2 141.37,135.14 141.18,135.14 141.12,135.2 141.12,136.23 141.44,136.55 141.44,137.21 141.49,137.26 142.33,137.26
N31436410 on BOTTOM (solid shape): 150.26,138.67 150.3,138.63 150.3,138.07 150.25,138.02 148.1,138.02 148.05,138.07 148.05,138.62 148.1,138.67 150.23,138.67
N31436413 on BOTTOM (solid shape): 149.07,137.25 149.07,136.62 148.42,135.96 148.42,135.33 148.29,135.2 148.17,135.2 148.1,135.27 148.1,137.26 148.16,137.32 149.01,137.32
N31436414 on BOTTOM (solid shape): 150.36,137.23 150.36,136.55 150.15,136.34 149.68,136.34 149.4,136.06 149.4,135.23 149.34,135.16 149.15,135.16 149.08,135.23 149.08,136.26 149.4,136.57 149.4,137.24 149.46,137.29 150.29,137.29
N31439632 on BOTTOM (solid shape): 117.36,138.65 117.4,138.61 117.4,138.05 117.35,138 115.2,138 115.15,138.05 115.15,138.6 115.2,138.65 117.33,138.65
N31439653 on BOTTOM (solid shape): 116.13,137.22 116.13,136.58 115.48,135.93 115.48,135.21 115.38,135.11 115.23,135.11 115.14,135.2 115.14,137.21 115.21,137.28 116.07,137.28
N31439658 on BOTTOM (solid shape): 117.41,137.19 117.41,136.51 117.21,136.3 116.74,136.3 116.46,136.02 116.46,135.19 116.38,135.11 116.22,135.11 116.14,135.19 116.14,136.22 116.44,136.52 116.44,137.23 116.46,137.25 117.35,137.25
N31452286 on BOTTOM (solid shape): 124.46,137.31 124.46,136.67 123.81,136.02 123.81,135.38 123.68,135.25 123.55,135.25 123.49,135.32 123.49,137.31 123.55,137.37 124.4,137.37
N31452288 on BOTTOM (solid shape): 125.69,138.74 125.73,138.7 125.73,138.14 125.68,138.09 123.53,138.09 123.48,138.14 123.48,138.69 123.53,138.74 125.66,138.74
N31452290 on BOTTOM (solid shape): 125.74,137.28 125.74,136.6 125.54,136.39 125.07,136.39 124.79,136.11 124.79,135.28 124.72,135.21 124.53,135.21 124.47,135.28 124.47,136.31 124.79,136.63 124.79,137.29 124.84,137.34 125.68,137.34
N31466143 on TOP (solid shape): 65.92,24.65 65.92,23 65.28,22.37 64.77,22.37 64.64,22.5 64.64,23.35 64.73,23.45 64.96,23.45 65.27,23.75 65.27,24.71 65.41,24.84 65.73,24.84
N31494164 on BOTTOM (solid shape): 157.3,131.81 157.3,130.41 157.17,130.28 156.54,130.28 156.48,130.35 156.48,131.36 156.16,131.68 155.21,131.68 155.14,131.74 155.14,132.25 155.21,132.31 156.79,132.31
N31494196 on BOTTOM (solid shape): 156.16,130.92 156.16,130.28 155.78,129.9 155.78,128.76 155.71,128.69 155.52,128.69 155.46,128.76 155.46,129.84 155.21,130.09 155.21,130.92 155.27,130.98 156.1,130.98
N31494209 on BOTTOM (solid shape): 158.57,131.17 158.57,129.33 158.16,128.92 156.44,128.92 156.22,128.69 156.03,128.69 155.97,128.76 155.97,129.52 156.1,129.65 157.56,129.65 157.87,129.96 157.87,131.17 157.94,131.23 158.51,131.23
N32112416 on TOP (solid shape): 235.54,59.85 235.54,57.24 235.49,57.2 233.91,57.2 233.75,57.36 233.75,59.9 233.91,60.07 235.31,60.07
N32112456 on TOP (solid shape): 245.98,75.18 245.98,73.53 245.89,73.43 245.89,72.67 245.82,72.6 244.93,72.6 244.87,72.67 244.87,74.32 245.31,74.76 245.31,75.21 245.38,75.27 245.89,75.27
N72585933 on TOP (solid shape): 75,46.81 74.43,46.24 73.73,46.24 73.66,46.31 73.66,47.32 73.35,47.64 73.35,48.66 75,48.66

Small or netless copper shapes (teardrops, artwork), in the pictures only: 113 on TOP, 301 on BOTTOM, 7 on IN1, 26 on IN2, 2 on IN5

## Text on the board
Ref Des/Silkscreen Bottom: VENDOR: | DC-IN | SPEAKER | BATTERY | KB | KB BL | TP | SSD-1 | SSD-2 | RTC | WLAN | CPU FAN | GPU FAN | HF | ONLY | FOR | DDR4 | DIMM1 | DIMM2
User.Comments: LAD581P | 2016-09-06 | 2017-09-06 | BAP00 | Win
Ref Des/Silkscreen Top: POWER | LOGO | VENDOR: | EDP | Pb | HF
IN5: IN5
GND4: GND4
BODY_CENTER: LAYER | NAME | L3 | L1 | L2 | L5 | L4 | L6 | L7 | L11 | L12 | L8 | L9 | L10 | LA-D581P | TOP | GND1 | IN2 | VCC | IN3 | IN4 | IN1 | GND3 | BOT | GND2 | GND4 | IN5 | LS-XXXXP
User.43: 4.5 / 5.2 | 3.5 / 6.7
User.44: FIGURE | SIZE | 8.0 | 20.0 | 22.0 | 28.0 | 30.0 | 35.0 | 36.0 | 39.0 | 90.0 | 102.0 | 110.0 | 114.0 | 126.0 | 150.0 | 217.0 | 24.0 | 43.0 | 47.0 | 63.0 | 197.0 | 49.0x28.0 | 55.0x24.0 | 63.0x35.0 | 67.0x31.0 | 69.0x28.0 | 75.0x24.0 | 79.0x28.0 | 79.0x31.0 | 94.0x24.0 | 94.0x28.0 | 102.0x31.0 | 110.0x94.0 | 126.0x106.0 | 130.0x110.0 | 138.0x122.0 | 33.0x20.0 | DRILL CHART: TOP to BOTTOM | ALL UNITS ARE IN MILS | TOLERANCE | +3.0/-3.0 | +2.0/-2.0 | PLATED | NON-PLATED | QTY | 10169 | 10 | 19 | 9 | 1 | 8 | 5 | 14 | 2 | 7 | 4
